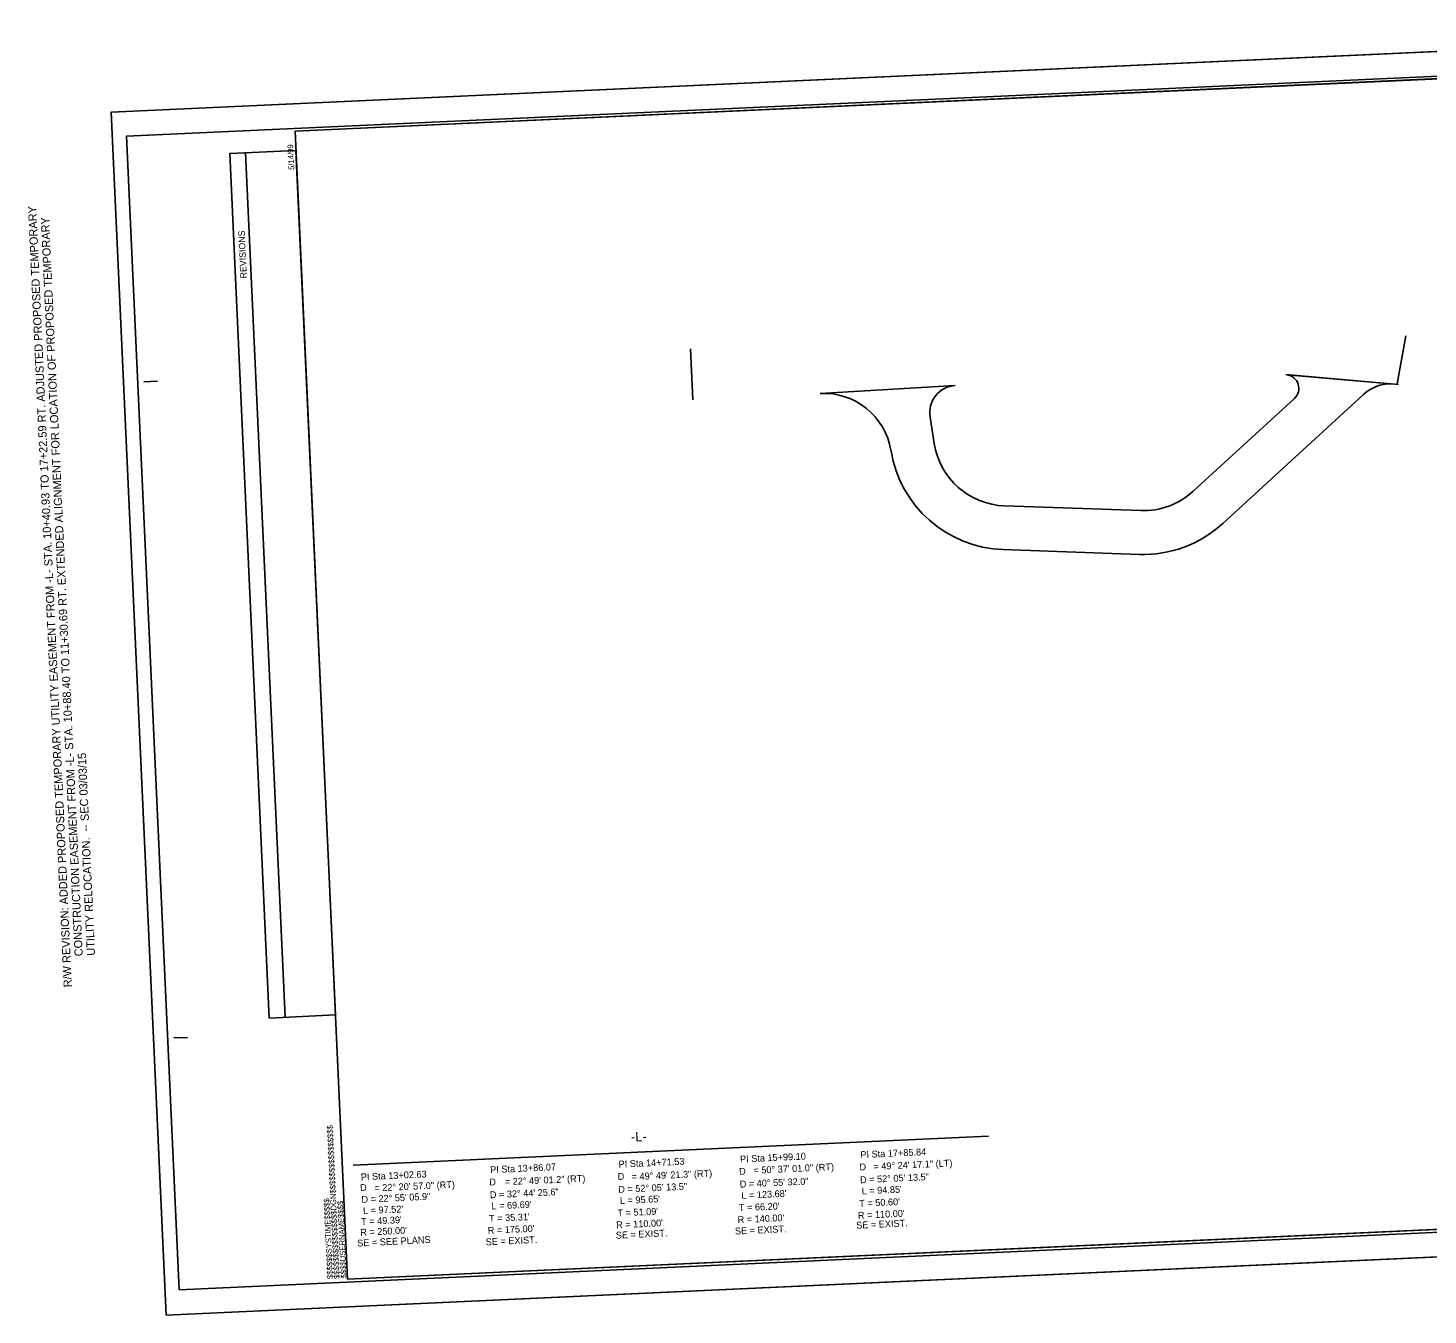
# Model space of a CAD drawing. Extents: x 1191090 to 1191897, y 892728 to 893199.
# Drawn here: x 1191090 to 1191602, y 892728 to 893199 of the extents above; entities that cross this region are included whole.
import ezdxf

# ---------------------------------------------------------------- set-up
doc = ezdxf.new("R2010")
doc.units = 0
for name, color, linetype in [('Prop DSN Text', 7, 'Continuous'), ('Prop EOT', 7, 'Continuous'), ('Prop Horizontal Alignment Curve and Spiral Data', 7, 'Continuous'), ('Prop Shade Light', 7, 'Continuous'), ('Sheet Block Revision CELL', 7, 'Continuous'), ('Sheet Border Standard 30in CELL', 7, 'Continuous'), ('Sheet Clip Boundary CELL', 7, 'Continuous'), ('Sheet Cutting Line CELL', 7, 'Continuous'), ('Sheet Plot Border Inside CELL', 7, 'Continuous'), ('Sheet Plot Border Outside CELL', 7, 'Continuous')]:
    doc.layers.add(name, color=color, linetype=linetype)

msp = doc.modelspace()

# ---------------------------------------------------------------- linework, layer by layer
at = {"layer": 'Prop EOT'}
for p, q in [((1191590.78, 893068.46), (1191594.01, 893086.02)), ((1191333.38, 893062.68), (1191332.53, 893081.3))]:
    msp.add_line(p, q, dxfattribs=at)
at = {"layer": 'Prop Horizontal Alignment Curve and Spiral Data'}
msp.add_line((1191209.21, 892782.98), (1191441.48, 892793.61), dxfattribs=at)
at = {"layer": 'Prop Shade Light'}
for p, q in [((1191550.12, 893071.88), (1191591.25, 893068.33)), ((1191588.5, 893068.56), (1191550.46, 893071.85)), ((1191379.88, 893065.01), (1191429.32, 893067.94)), ((1191429.32, 893067.94), (1191379.88, 893065.01)), ((1191553.24, 893063.2), (1191516.27, 893029.27)), ((1191527.09, 893017.48), (1191578.45, 893064.62)), ((1191421.61, 893046.69), (1191420.08, 893056.4)), ((1191497.07, 893022.18), (1191447.33, 893023.92)), ((1191446.78, 893007.93), (1191496.51, 893006.19))]:
    msp.add_line(p, q, dxfattribs=at)
msp.add_lwpolyline([(1191405.81, 893044.2), (1191405.81, 893044.2)], dxfattribs=at)
for centre, radius, start, end in [((1191549.86, 893066.88), 5, 312.5411, 83.0925), ((1191429.95, 893057.96), 10, 93.6582, 188.9764), ((1191588.59, 893053.57), 15, 90.3526, 132.5411), ((1191381.15, 893040.04), 25, 9.5636, 92.9116), ((1191448.28, 893050.91), 27, 188.9764, 267.9944), ((1191448.28, 893050.91), 43, 188.9764, 189.1922), ((1191381.15, 893040.04), 25, 9.1923, 9.1924), ((1191448.28, 893050.91), 43, 189.1923, 267.9944), ((1191498.01, 893049.17), 27, 267.9944, 312.5411), ((1191498.01, 893049.17), 43, 267.9944, 312.5411)]:
    msp.add_arc(centre, radius, start, end, dxfattribs=at)
at = {"layer": 'Sheet Block Revision CELL'}
msp.add_line((1191184.39, 892837.03), (1191169.94, 893152.96), dxfattribs=at)
msp.add_lwpolyline([(1191178.58, 892836.76), (1191164.12, 893152.69), (1191188.32, 893153.8), (1191202.77, 892837.87)], close=True, dxfattribs=at)
at = {"layer": 'Sheet Border Standard 30in CELL'}
for p, q in [((1191188.4, 893160.85), (1191188.4, 893160.85)), ((1191132.73, 893069.21), (1191137.72, 893069.44)), ((1191143.69, 892829.46), (1191148.69, 892829.69))]:
    msp.add_line(p, q, dxfattribs=at)
msp.add_lwpolyline([(1191787.37, 893188.26), (1191188, 893160.84), (1191207.19, 892741.27), (1191806.56, 892768.7)], close=True, dxfattribs=at)
at = {"layer": 'Sheet Clip Boundary CELL'}
msp.add_lwpolyline([(1191207.19, 892741.27), (1191188, 893160.84), (1191701.28, 893184.54), (1191704.74, 893109.58), (1191790.64, 893113.55), (1191806.56, 892768.7), (1191506.88, 892754.98)], close=True, dxfattribs=at)
at = {"layer": 'Sheet Cutting Line CELL'}
for p, q in [((1191793.71, 893198.56), (1191120.81, 893167.77)), ((1191120.81, 893167.77), (1191140.92, 892728.23)), ((1191140.92, 892728.23), (1191813.81, 892759.02))]:
    msp.add_line(p, q, dxfattribs=at)
at = {"layer": 'Sheet Plot Border Inside CELL'}
msp.add_lwpolyline([(1191792.32, 893189.5), (1191126.41, 893159.04), (1191145.7, 892737.44), (1191811.61, 892767.91)], close=True, dxfattribs=at)
at = {"layer": 'Sheet Plot Border Outside CELL'}
msp.add_lwpolyline([(1191793.71, 893198.56), (1191120.81, 893167.77), (1191140.92, 892728.23), (1191813.81, 892759.02)], close=True, dxfattribs=at)

# ---------------------------------------------------------------- texts
at = {"layer": 'Prop DSN Text'}
for s, p in [('R/W REVISION: ADDED PROPOSED TEMPORARY UTILITY EASEMENT FROM -L- STA. 10+40.93 TO 17+22.59 RT. ADJUSTED PROPOSED TEMPORARY', (1191106.46, 892848.05)), ('          CONSTRUCTION EASEMENT FROM -L- STA. 10+88.40 TO 11+30.69 RT. EXTENDED ALIGNMENT FOR LOCATION OF PROPOSED TEMPORARY ', (1191110.96, 892848.25)), ('          UTILITY RELOCATION.  -- SEC 03/03/15', (1191115.45, 892848.46))]:
    msp.add_text(s, height=3, rotation=92.6195, dxfattribs=at).set_placement(p)
at = {"layer": 'Prop Horizontal Alignment Curve and Spiral Data'}
for s, height, rotation, p in [('-L-', 3.5, 2.5289, (1191310.87, 892791.56)), ('PI Sta 14+71.53', 2.5, 2.621, (1191306.31, 892782.07)), ('PI Sta 15+99.10', 2.5, 2.621, (1191350.69, 892783.96)), ('PI Sta 17+85.84', 2.5, 2.621, (1191394.67, 892785.56)), ('= 49%%d 24\' 17.1" (LT)', 2.5, 2.621, (1191399.43, 892781.23)), ('PI Sta 13+02.63', 2.5, 2.621, (1191212.1, 892777.42)), ('PI Sta 13+86.07', 2.5, 2.621, (1191259.38, 892780.06)), ('D', 2.5, 2.621, (1191305.97, 892777.56)), ('= 49%%d 49\' 21.3" (RT)', 2.5, 2.621, (1191311.08, 892777.5)), ('D', 2.5, 2.621, (1191350.35, 892779.45)), ('= 50%%d 37\' 01.0" (RT)', 2.5, 2.621, (1191355.58, 892779.84)), ('D', 2.5, 2.621, (1191394.34, 892781.05)), ('D = 52%%d 05\' 13.5"', 2.5, 2.621, (1191394.55, 892776.37)), ('D', 2.5, 2.621, (1191211.82, 892773.51)), ('= 22%%d 20\' 57.0" (RT)', 2.5, 2.621, (1191217.05, 892773.39)), ('D', 2.5, 2.621, (1191259.05, 892775.55)), ('= 22%%d 49\' 01.2" (RT)', 2.5, 2.4459, (1191264.71, 892775.68)), ('D = 52%%d 05\' 13.5"', 2.5, 2.621, (1191306.19, 892772.88)), ('D = 40%%d 55\' 32.0"', 2.5, 2.621, (1191350.57, 892774.77)), ("L = 94.85'", 2.5, 2.621, (1191395.15, 892772.28)), ('D = 22%%d 55\' 05.9"', 2.5, 2.621, (1191212.33, 892769.22)), ('D = 32%%d 44\' 25.6"', 2.5, 2.621, (1191259.26, 892770.87)), ("L = 69.69'", 2.5, 2.621, (1191259.86, 892766.77)), ("L = 95.65'", 2.5, 2.621, (1191306.79, 892768.78)), ("L = 123.68'", 2.5, 2.621, (1191351.16, 892770.68)), ("T = 50.60'", 2.5, 2.621, (1191394.26, 892767.75)), ("L = 97.52'", 2.5, 2.621, (1191212.91, 892765.08)), ("T = 35.31'", 2.5, 2.621, (1191258.98, 892762.24)), ("T = 51.09'", 2.5, 2.621, (1191305.9, 892764.25)), ("R = 140.00'", 2.5, 2.621, (1191349.8, 892761.78)), ("T = 66.20'", 2.5, 2.621, (1191350.28, 892766.15)), ("R = 110.00'", 2.5, 2.621, (1191393.78, 892763.38)), ("R = 250.00'", 2.5, 2.621, (1191211.87, 892757.18)), ("T = 49.39'", 2.5, 2.621, (1191212.23, 892761.13)), ("R = 175.00'", 2.5, 2.621, (1191258.49, 892757.87)), ('SE = EXIST.', 2.5, 2.621, (1191305.29, 892756.11)), ("R = 110.00'", 2.5, 2.621, (1191305.42, 892759.89)), ('SE = EXIST.', 2.5, 2.621, (1191348.82, 892757.63)), ('SE = EXIST.', 2.5, 2.621, (1191393.13, 892759.77)), ('SE = SEE PLANS', 2.5, 2.926, (1191210.77, 892753.23)), ('SE = EXIST.', 2.5, 2.621, (1191257.75, 892753.69))]:
    msp.add_text(s, height=height, rotation=rotation, dxfattribs=at).set_placement(p)
at = {"layer": 'Sheet Block Revision CELL'}
msp.add_text('REVISIONS', height=2.4, rotation=92.6195, dxfattribs=at).set_placement((1191170.41, 893107.13))
at = {"layer": 'Sheet Border Standard 30in CELL'}
for s, p in [('5/14/99', (1191187.74, 893146.73)), ('$$$$$$$$$$$$$$$$DGN$$$$$$$$$$$$$$$$', (1191204.32, 892741.48)), ('$$$$$$SYSTIME$$$$$', (1191201.9, 892741.45)), ('$$$$USERNAME$$$$', (1191206.83, 892741.64))]:
    msp.add_text(s, height=2.1, rotation=92.6195, dxfattribs=at).set_placement(p)

doc.saveas('drawing.dxf')
